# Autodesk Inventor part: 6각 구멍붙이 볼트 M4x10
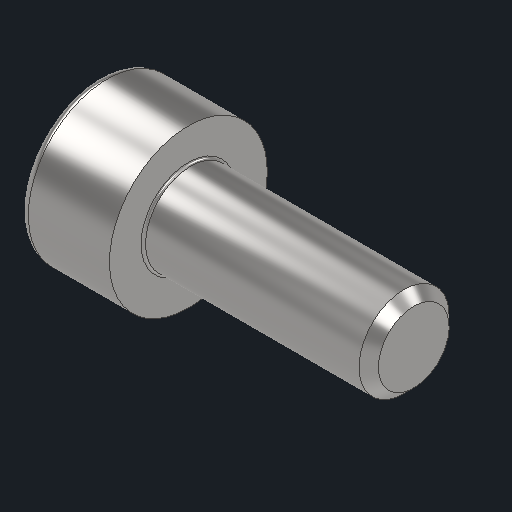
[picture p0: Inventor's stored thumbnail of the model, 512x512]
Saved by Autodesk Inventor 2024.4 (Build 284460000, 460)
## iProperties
Created: 2025-10
Part Number: 6각 구멍붙이 볼트 M4x10
Material: 강철, 연강
Description: 6각머리 태핑 나사
Document SubType Name: Modeling
Designer: user
Density: 7.85 g/cm^3
Appearance: 기본값
Author: jhkim
Sending System: Autodesk Inventor 2026
Preprocessor: ST-DEVELOPER v20.1
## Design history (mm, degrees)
feature "Solid1"
node "솔리드1"
